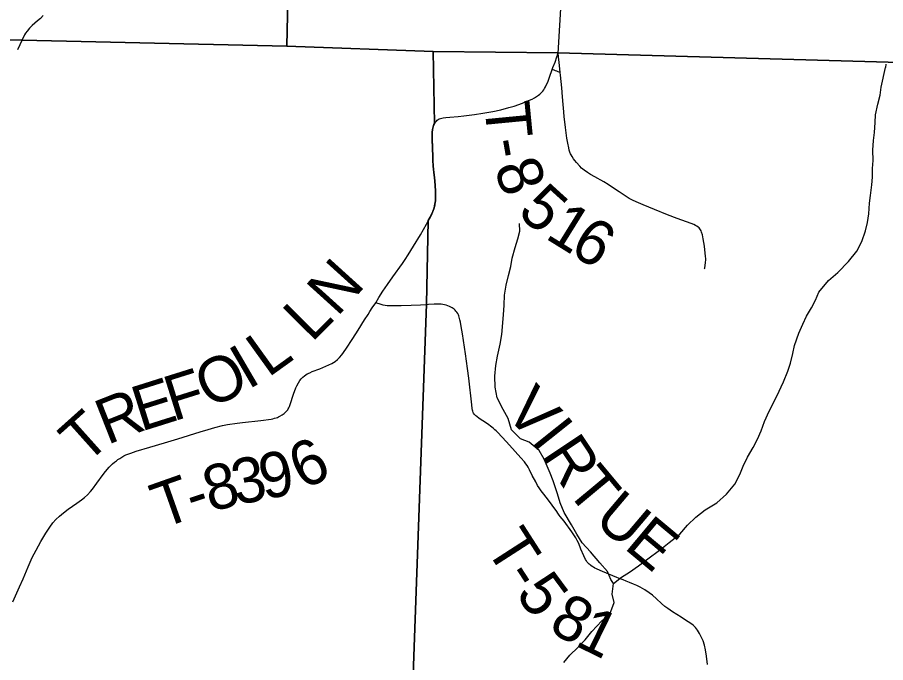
# Model space of a CAD drawing. Extents: x -14196 to 143, y -6096 to 28.
# Drawn here: x 61.862 to 62.952, y 18.007 to 18.818 of the extents above; entities that cross this region are included whole.
import ezdxf

# ---------------------------------------------------------------- set-up
doc = ezdxf.new("R2010")
doc.units = 0
for name, color, linetype in [('GM_X_Corporation', 7, 'Continuous'), ('GM_X_Minor_River', 7, 'Continuous'), ('GM_X_Township_Road', 7, 'Continuous'), ('GM_X_Township_Road_Text', 7, 'Continuous')]:
    doc.layers.add(name, color=color, linetype=linetype)

msp = doc.modelspace()

# ---------------------------------------------------------------- linework, layer by layer
at = {"layer": 'GM_X_Corporation'}
msp.add_lwpolyline([(64.9028, 18.7286), (64.9028, 23.6985), (62.6174, 23.6985), (62.6129, 23.4358), (62.306, 23.4402), (62.2824, 22.5866), (62.2815, 22.5484), (62.2751, 22.2884), (62.2487, 21.1358), (62.2323, 20.4208), (62.2235, 19.866), (62.1999, 18.7816), (62.384, 18.775), (62.5403, 18.7731), (63.0887, 18.7577), (63.6879, 18.7414), (64.3696, 18.7343), (64.4266, 18.7347)], close=True, dxfattribs=at)
for points in [[(61.8121, 18.7902), (62.1999, 18.7816), (62.2235, 19.866)], [(61.8121, 18.7902), (62.1999, 18.7816), (62.384, 18.775), (62.5403, 18.7731), (63.0887, 18.7577)], [(63.0887, 18.7577), (62.5403, 18.7731), (62.384, 18.775), (62.1999, 18.7816), (61.8121, 18.7902)], [(62.3347, 17.3291), (62.3753, 18.4575), (62.3776, 18.5626), (62.38, 18.5669), (62.3819, 18.5708), (62.3834, 18.5742), (62.385, 18.5788), (62.386, 18.583), (62.3866, 18.5873), (62.3869, 18.5923), (62.3869, 18.599), (62.3864, 18.607), (62.3855, 18.6168), (62.3848, 18.6229), (62.3844, 18.6272), (62.384, 18.6309), (62.3838, 18.6334), (62.3836, 18.6358), (62.3833, 18.6439), (62.3829, 18.6532), (62.3825, 18.6662), (62.3826, 18.6731), (62.383, 18.6768), (62.3837, 18.6805), (62.3842, 18.6821), (62.3848, 18.6834), (62.3854, 18.6846), (62.384, 18.775), (62.1999, 18.7816), (61.8121, 18.7902)], [(63.0887, 18.7577), (62.5403, 18.7731), (62.384, 18.775), (62.3854, 18.6846), (62.3848, 18.6834), (62.3842, 18.6821), (62.3837, 18.6805), (62.383, 18.6768), (62.3826, 18.6731), (62.3825, 18.6662), (62.3829, 18.6532), (62.3833, 18.6439), (62.3836, 18.6358), (62.3838, 18.6334), (62.384, 18.6309), (62.3844, 18.6272), (62.3848, 18.6229), (62.3855, 18.6168), (62.3864, 18.607), (62.3869, 18.599), (62.3869, 18.5923), (62.3866, 18.5873), (62.386, 18.583), (62.385, 18.5788), (62.3834, 18.5742), (62.3819, 18.5708), (62.38, 18.5669), (62.3776, 18.5626), (62.3753, 18.4575), (62.3347, 17.3291)]]:
    msp.add_lwpolyline(points, dxfattribs=at)
at = {"layer": 'GM_X_Minor_River'}
for points in [[(61.8943, 18.8202), (61.8909, 18.8164), (61.8868, 18.8133), (61.8838, 18.8106), (61.8804, 18.8075), (61.8785, 18.806), (61.877, 18.8041), (61.874, 18.8003), (61.8721, 18.798), (61.8707, 18.7957), (61.8617, 18.7772)], [(62.9158, 18.524), (62.9221, 18.5362), (62.9269, 18.5499), (62.9295, 18.5602), (62.9309, 18.5712), (62.9316, 18.5844), (62.933, 18.5939), (62.9348, 18.6076), (62.9355, 18.6171), (62.9357, 18.6281), (62.9364, 18.638), (62.9359, 18.6512), (62.937, 18.663), (62.938, 18.6733), (62.9391, 18.6858), (62.9394, 18.6953), (62.9423, 18.7089), (62.9452, 18.72), (62.9463, 18.7302), (62.9517, 18.7548)], [(62.9525, 18.7588), (62.9517, 18.7549)], [(62.6105, 18.1069), (62.6071, 18.1118), (62.6028, 18.122), (62.5932, 18.1329), (62.5814, 18.1465), (62.5711, 18.1581), (62.5642, 18.1687), (62.5576, 18.1804), (62.5484, 18.1959), (62.5434, 18.208), (62.5399, 18.2193), (62.5345, 18.2356), (62.531, 18.2454), (62.5233, 18.2632), (62.5171, 18.2738), (62.5045, 18.2843), (62.4935, 18.2887), (62.4821, 18.3), (62.4782, 18.314), (62.4716, 18.3254), (62.4643, 18.3401), (62.4616, 18.3533), (62.4615, 18.3674), (62.4625, 18.3807), (62.4647, 18.3924), (62.4679, 18.4076), (62.4701, 18.4194), (62.4722, 18.4441), (62.4729, 18.4562), (62.4735, 18.4691), (62.4757, 18.4816), (62.4786, 18.4938), (62.4812, 18.5048), (62.483, 18.5154), (62.487, 18.5287), (62.4904, 18.5398), (62.4925, 18.5493), (62.4921, 18.5591)], [(62.5481, 18.0075), (62.5556, 18.017), (62.5657, 18.0266), (62.5747, 18.0361), (62.583, 18.0464), (62.5957, 18.0598), (62.6059, 18.0682), (62.6111, 18.083), (62.6087, 18.0936), (62.6105, 18.1069), (62.6203, 18.1149), (62.6305, 18.121), (62.6418, 18.1291), (62.6519, 18.1364), (62.6696, 18.1501), (62.6801, 18.1582), (62.6937, 18.1689), (62.7034, 18.18), (62.7136, 18.1903), (62.7253, 18.1995), (62.7399, 18.2083), (62.7524, 18.219), (62.7625, 18.2316), (62.7688, 18.2438), (62.7733, 18.2541), (62.7785, 18.2655), (62.7856, 18.2777), (62.7912, 18.2883), (62.7956, 18.2986), (62.8001, 18.3104), (62.8057, 18.3233), (62.8154, 18.3423), (62.8239, 18.3599), (62.8291, 18.3735), (62.8324, 18.3834), (62.8354, 18.3956), (62.8376, 18.4059), (62.8431, 18.4214), (62.848, 18.4325), (62.8528, 18.4424), (62.8591, 18.453), (62.864, 18.4626), (62.8681, 18.4725), (62.8805, 18.4873), (62.8921, 18.4973), (62.9053, 18.5114), (62.9158, 18.524)]]:
    msp.add_lwpolyline(points, dxfattribs=at)
at = {"layer": 'GM_X_Township_Road'}
for points in [[(62.5445, 18.8434), (62.5405, 18.7725)], [(62.5335, 18.7521), (62.5343, 18.7547), (62.5369, 18.7617), (62.5392, 18.7684), (62.5399, 18.7705), (62.5405, 18.7725)], [(62.5435, 18.7484), (62.542, 18.7614), (62.5414, 18.768), (62.5411, 18.7693), (62.5405, 18.7725)], [(62.3869, 18.6861), (62.3879, 18.6874), (62.389, 18.6885), (62.3902, 18.6894), (62.3915, 18.6902), (62.3929, 18.6908), (62.3947, 18.6914), (62.3965, 18.6918), (62.3999, 18.6922), (62.4048, 18.6926), (62.4154, 18.6933), (62.4222, 18.694), (62.4357, 18.6957), (62.4461, 18.6973), (62.459, 18.6996), (62.4687, 18.7017), (62.4789, 18.7044), (62.4854, 18.7063), (62.4959, 18.7101), (62.5017, 18.7124), (62.508, 18.7152), (62.5112, 18.7168), (62.5138, 18.7183), (62.516, 18.7199), (62.5178, 18.7213), (62.5193, 18.7228), (62.5205, 18.724), (62.5216, 18.7253), (62.5227, 18.7269), (62.5238, 18.7286), (62.5249, 18.7306), (62.5281, 18.7376), (62.5301, 18.7427), (62.5335, 18.7521)], [(62.5435, 18.7484), (62.5409, 18.7495), (62.5391, 18.7502), (62.5375, 18.7508), (62.5357, 18.7515), (62.5335, 18.7521)], [(62.7247, 18.5021), (62.7249, 18.503), (62.7259, 18.5101), (62.7261, 18.5131), (62.7261, 18.515), (62.726, 18.5173), (62.7245, 18.5304), (62.7231, 18.5396), (62.7221, 18.5445), (62.721, 18.548), (62.7203, 18.5496), (62.7196, 18.5511), (62.7189, 18.5522), (62.7178, 18.5534), (62.7166, 18.5545), (62.7151, 18.5555), (62.7134, 18.5565), (62.7112, 18.5575), (62.7077, 18.5588), (62.6904, 18.5651), (62.6783, 18.5698), (62.6618, 18.5764), (62.6475, 18.5823), (62.6387, 18.5862), (62.6342, 18.5883), (62.6302, 18.5905), (62.6263, 18.5928), (62.6224, 18.5953), (62.6173, 18.5986), (62.6117, 18.6025), (62.6037, 18.6077), (62.5982, 18.6111), (62.5945, 18.6132), (62.5935, 18.6138), (62.5908, 18.6153), (62.587, 18.6174), (62.5816, 18.6204), (62.5775, 18.6231), (62.5733, 18.6261), (62.5703, 18.6286), (62.568, 18.6308), (62.5637, 18.6356), (62.5617, 18.6379), (62.56, 18.6403), (62.5584, 18.6429), (62.5572, 18.645), (62.5565, 18.6465), (62.5556, 18.6487), (62.5548, 18.651), (62.5542, 18.6539), (62.553, 18.6596), (62.5519, 18.6661), (62.5509, 18.6726), (62.55, 18.6793), (62.5491, 18.6867), (62.5485, 18.6928), (62.548, 18.699), (62.5472, 18.7083), (62.5463, 18.7181), (62.5453, 18.7292), (62.5445, 18.7371), (62.5438, 18.745), (62.5435, 18.7484)], [(62.3778, 18.562), (62.3802, 18.5664), (62.3821, 18.5702), (62.3836, 18.5736), (62.3852, 18.5783), (62.3862, 18.5825), (62.3868, 18.5868), (62.3871, 18.5917), (62.3871, 18.5985), (62.3866, 18.6065), (62.3857, 18.6162), (62.385, 18.6224), (62.3846, 18.6267), (62.3842, 18.6303), (62.384, 18.6328), (62.3838, 18.6353), (62.3835, 18.6433), (62.3831, 18.6527), (62.3827, 18.6657), (62.3828, 18.6725), (62.3832, 18.6763), (62.3839, 18.6799), (62.3844, 18.6816), (62.385, 18.6828), (62.3856, 18.6841), (62.3864, 18.6854), (62.3869, 18.6861)], [(62.3117, 18.4595), (62.3156, 18.466), (62.3208, 18.4738), (62.3264, 18.4822), (62.3334, 18.4921), (62.3452, 18.5088), (62.3487, 18.5139), (62.3524, 18.5196), (62.3592, 18.5305), (62.3678, 18.5446), (62.3754, 18.5579), (62.3778, 18.562)], [(61.856, 18.084), (61.8645, 18.1027), (61.8688, 18.1129), (61.8752, 18.1276), (61.8805, 18.1394), (61.8852, 18.1487), (61.891, 18.1595), (61.8973, 18.17), (61.9023, 18.1777), (61.9064, 18.1831), (61.91, 18.1872), (61.9145, 18.1915), (61.9197, 18.1958), (61.9257, 18.2002), (61.9362, 18.2076), (61.9422, 18.212), (61.9461, 18.215), (61.9498, 18.2183), (61.9536, 18.2224), (61.9559, 18.2253), (61.9614, 18.2328), (61.9694, 18.2438), (61.9724, 18.2477), (61.977, 18.2528), (61.9813, 18.2571), (61.9836, 18.2591), (61.986, 18.2611), (61.988, 18.2625), (61.9902, 18.2639), (61.9928, 18.2655), (61.9956, 18.2671), (61.9981, 18.2683), (62.0006, 18.2694), (62.004, 18.2706), (62.011, 18.273), (62.0281, 18.2782), (62.0465, 18.2837), (62.0631, 18.2887), (62.0914, 18.2974), (62.1014, 18.3004), (62.1097, 18.3029), (62.1194, 18.3052), (62.1255, 18.3064), (62.1378, 18.3082), (62.1446, 18.3089), (62.1674, 18.3116), (62.1803, 18.3134), (62.1824, 18.3138), (62.1845, 18.3143), (62.1866, 18.3149), (62.1883, 18.3155), (62.1898, 18.3161), (62.1914, 18.3171), (62.1941, 18.3187), (62.1966, 18.3203), (62.1981, 18.3216), (62.1993, 18.3227), (62.2004, 18.3239), (62.2012, 18.3251), (62.2019, 18.3262), (62.2025, 18.3273), (62.2033, 18.329), (62.2042, 18.3316), (62.2085, 18.3445), (62.2116, 18.3525), (62.2126, 18.355), (62.2146, 18.3587), (62.2165, 18.3618), (62.2182, 18.364), (62.2201, 18.366), (62.2222, 18.3678), (62.2238, 18.3689), (62.2258, 18.3701), (62.2288, 18.3716), (62.232, 18.3729), (62.2417, 18.3766), (62.2567, 18.3833), (62.2589, 18.3845), (62.2609, 18.3858), (62.2638, 18.3881), (62.2664, 18.3907), (62.2692, 18.3941), (62.2742, 18.4012), (62.283, 18.4145), (62.2896, 18.425), (62.2978, 18.4381), (62.3021, 18.4448), (62.3044, 18.4484), (62.3073, 18.4529), (62.3117, 18.4595)], [(62.3745, 18.4569), (62.3678, 18.4565), (62.3564, 18.4558), (62.3437, 18.4556), (62.3349, 18.4555), (62.3292, 18.4555), (62.3261, 18.4557), (62.3238, 18.456), (62.3211, 18.4565), (62.3184, 18.4573), (62.3117, 18.4595)], [(62.7283, 18.0052), (62.7271, 18.0156), (62.7258, 18.0235), (62.7245, 18.0294), (62.7229, 18.0347), (62.721, 18.0392), (62.7185, 18.0441), (62.7159, 18.0482), (62.7133, 18.0515), (62.7103, 18.0546), (62.7074, 18.0568), (62.7043, 18.0588), (62.7007, 18.061), (62.6955, 18.0644), (62.6898, 18.0681), (62.6846, 18.0714), (62.6784, 18.0755), (62.6749, 18.0781), (62.6706, 18.0817), (62.6642, 18.0875), (62.6591, 18.0921), (62.6552, 18.0951), (62.6495, 18.0988), (62.644, 18.1022), (62.6397, 18.1044), (62.6355, 18.1062), (62.6305, 18.1083), (62.6261, 18.11), (62.6224, 18.1113), (62.6189, 18.1127), (62.6145, 18.1145), (62.6046, 18.1186), (62.5936, 18.1233), (62.589, 18.1251), (62.587, 18.1262), (62.5851, 18.1272), (62.5836, 18.1281), (62.582, 18.1293), (62.5809, 18.1303), (62.5798, 18.1313), (62.5785, 18.1325), (62.5774, 18.1337), (62.5763, 18.1353), (62.5753, 18.1371), (62.573, 18.1415), (62.5694, 18.15), (62.5666, 18.1569), (62.5647, 18.161), (62.5631, 18.1642), (62.5615, 18.1669), (62.5581, 18.1719), (62.5482, 18.1851), (62.5434, 18.1912), (62.5423, 18.1927), (62.5405, 18.1952), (62.5391, 18.1972), (62.5333, 18.2052), (62.5285, 18.2116), (62.5229, 18.219), (62.5196, 18.2232), (62.517, 18.227), (62.515, 18.2301), (62.5126, 18.2344), (62.5083, 18.2426), (62.5047, 18.2498), (62.5032, 18.2528), (62.5019, 18.255), (62.5004, 18.2571), (62.4984, 18.2596), (62.494, 18.2647), (62.487, 18.2726), (62.4759, 18.2847), (62.4648, 18.2967), (62.463, 18.2984), (62.4612, 18.3), (62.4592, 18.3018), (62.456, 18.3044), (62.4539, 18.3061), (62.4507, 18.3081), (62.4416, 18.3141), (62.4387, 18.3164), (62.4374, 18.3175), (62.4361, 18.3186), (62.4353, 18.3196), (62.4346, 18.3208), (62.4341, 18.3217), (62.4335, 18.3232), (62.4332, 18.3247), (62.433, 18.3265), (62.4323, 18.3313), (62.4285, 18.3645), (62.4268, 18.3768), (62.4244, 18.3953), (62.4208, 18.4205), (62.4192, 18.4297), (62.4182, 18.435), (62.4175, 18.438), (62.416, 18.443), (62.4155, 18.4444), (62.4147, 18.446), (62.4136, 18.4475), (62.4124, 18.449), (62.4113, 18.4503), (62.4102, 18.4513), (62.4089, 18.4522), (62.4076, 18.4531), (62.4059, 18.454), (62.4042, 18.4549), (62.4023, 18.4556), (62.4002, 18.4562), (62.3982, 18.4568), (62.396, 18.4572), (62.394, 18.4575), (62.3915, 18.4577), (62.3883, 18.4576), (62.385, 18.4575), (62.3782, 18.4572), (62.3755, 18.457), (62.3745, 18.4569)]]:
    msp.add_lwpolyline(points, dxfattribs=at)

# ---------------------------------------------------------------- texts
at = {"layer": 'GM_X_Township_Road_Text'}
for s, rotation, p in [('T', 275.5068, (62.448, 18.7096)), ('-', 280.0043, (62.4527, 18.6625)), ('8', 289.9876, (62.4596, 18.6291)), ('5', 317.8002, (62.4881, 18.5715)), ('1', 328.1933, (62.523, 18.5412)), ('6', 328.6431, (62.5532, 18.5225)), ('N', 47.8531, (62.2632, 18.4407)), ('L', 45.244, (62.2313, 18.4085)), ('L', 35.7142, (62.1765, 18.3647)), ('I', 30.3142, (62.1514, 18.3497)), ('O', 26.7165, (62.1033, 18.3254)), ('F', 17.4252, (62.0574, 18.3102)), ('E', 17.4849, (62.0169, 18.2974)), ('V', 313.7404, (62.4718, 18.3209)), ('R', 21.5528, (61.9745, 18.2806)), ('T', 41.8165, (61.9473, 18.255)), ('I', 308.5672, (62.5055, 18.2858)), ('6', 26.0276, (62.2206, 18.2238)), ('R', 303.7225, (62.5193, 18.2685)), ('3', 11.0589, (62.1366, 18.2051)), ('9', 11.3259, (62.1713, 18.2119)), ('8', 15.0347, (62.1039, 18.1963)), ('T', 309.7313, (62.549, 18.2246)), ('T', 19.465, (62.0427, 18.1753)), ('-', 18.0153, (62.0824, 18.1893)), ('U', 319.7713, (62.5837, 18.1843)), ('E', 320.1391, (62.6222, 18.1518)), ('T', 302.7522, (62.4483, 18.1523)), ('-', 303.0489, (62.4715, 18.1163)), ('5', 306.4905, (62.4863, 18.0937)), ('8', 330.9668, (62.5269, 18.0482)), ('1', 333.879, (62.5603, 18.0298))]:
    msp.add_text(s, height=0.0568, rotation=rotation, dxfattribs=at).set_placement(p)

doc.saveas('drawing.dxf')
